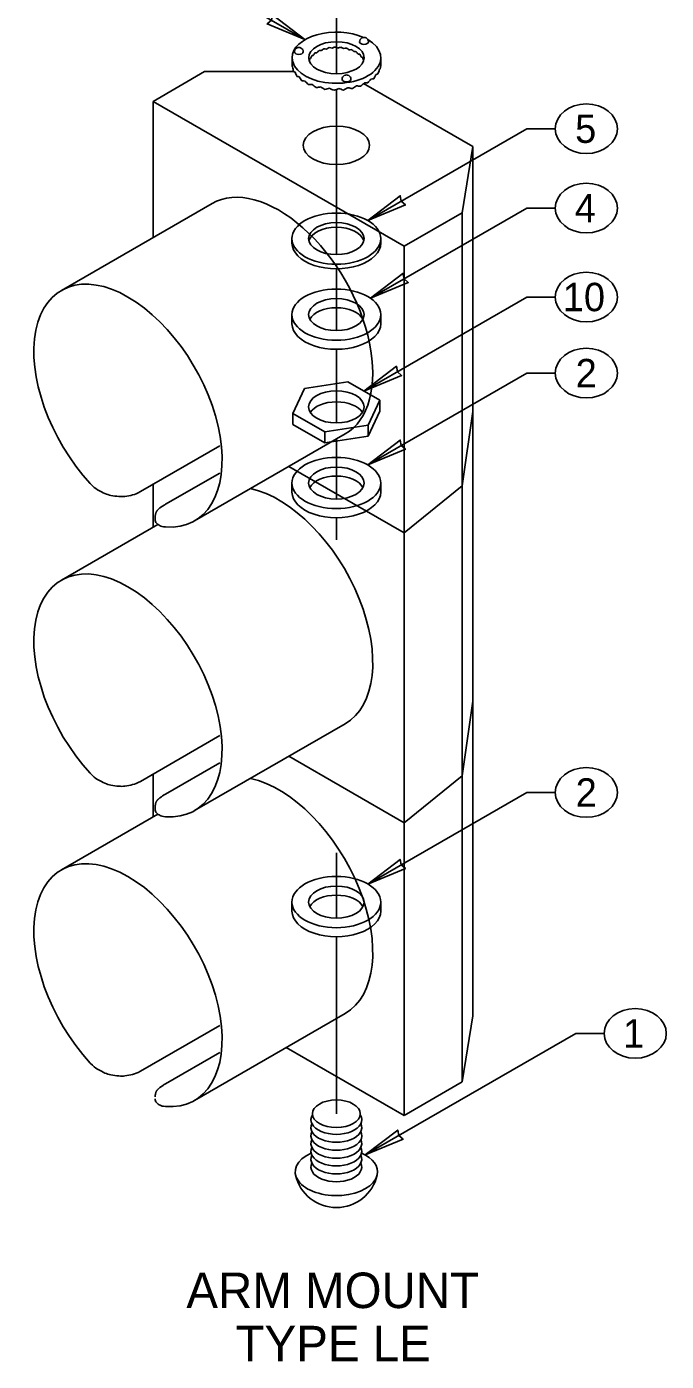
# Model space of a CAD drawing. Extents: x 99862 to 104211, y 98939 to 105076.
# Drawn here: x 100823 to 101184, y 100882 to 101635 of the extents above; entities that cross this region are included whole.
import ezdxf

# ---------------------------------------------------------------- set-up
doc = ezdxf.new("R2010")
doc.units = 0
for name, color, linetype in [('Level 1', 7, 'Continuous'), ('Level 10', 7, 'Continuous'), ('Level 15', 7, 'Continuous'), ('Level 19', 7, 'Continuous'), ('Level 2', 7, 'Continuous'), ('Level 20', 7, 'Continuous'), ('Level 26', 7, 'Continuous'), ('Level 4', 7, 'Continuous'), ('Level 5', 7, 'Continuous'), ('Level 7', 7, 'Continuous')]:
    doc.layers.add(name, color=color, linetype=linetype)

msp = doc.modelspace()

# ---------------------------------------------------------------- linework, layer by layer
at = {"layer": 'Level 1'}
msp.add_arc((100997.83, 100992.61), 23.6, 192.74663, 347.25337, dxfattribs=at)
msp.add_ellipse((100997.83, 101021.85), major_axis=(-13.49, 0), ratio=0.57735, dxfattribs=at)
for centre, major_axis, start_param, end_param in [((100997.83, 101018.51), (14.31, 0), 2.795302, 6.629476), ((100997.83, 101014.06), (14.31, 0), 2.86885, 6.555928), ((100997.83, 101009.52), (14.31, 0), 2.86338, 6.561398), ((100997.83, 101005.07), (14.31, 0), 2.86885, 6.555928), ((100997.83, 101000.71), (14.31, 0), 2.874311, 6.550467), ((100997.83, 100989.14), (23.21, 0), 2.229419, 6.153315), ((100997.83, 100996.26), (14.31, 0), 2.86885, 6.555928), ((100997.83, 100991.81), (14.31, 0), 2.86885, 6.555928), ((100997.83, 100989.14), (23.21, 0), 6.153315, 7.195359)]:
    msp.add_ellipse(centre, major_axis=major_axis, ratio=0.57735, start_param=start_param, end_param=end_param, dxfattribs=at)
at = {"layer": 'Level 10'}
for p, q in [((100979.93, 101430.54), (100973.38, 101416.43)), ((101004.38, 101434.32), (100979.93, 101430.54)), ((101022.28, 101423.99), (101004.38, 101434.32)), ((101015.73, 101409.87), (101022.28, 101423.99)), ((101022.28, 101423.99), (101022.28, 101417.79)), ((100973.38, 101416.43), (100973.38, 101410.23)), ((100973.38, 101416.43), (100991.28, 101406.09)), ((101015.73, 101403.67), (101022.28, 101417.79)), ((100973.38, 101410.23), (100991.28, 101399.89)), ((100991.28, 101406.09), (101015.73, 101409.87)), ((101015.73, 101409.87), (101015.73, 101403.67)), ((100991.28, 101406.09), (100991.28, 101399.89)), ((100991.28, 101399.89), (101015.73, 101403.67))]:
    msp.add_line(p, q, dxfattribs=at)
msp.add_ellipse((100997.83, 101420.21), major_axis=(15.66, 0), ratio=0.57735, dxfattribs=at)
msp.add_ellipse((100997.83, 101414.01), major_axis=(15.66, 0), ratio=0.57735, start_param=0.349873, end_param=2.791719, dxfattribs=at)
at = {"layer": 'Level 15'}
for p, q in [((100980.1, 101627.23), (100921.56, 101661.03)), ((100997.83, 101608), (100997.83, 101642.43)), ((100997.83, 101506.04), (100997.83, 101599.12)), ((101015.5, 101525.27), (101105.13, 101577.02)), ((101121.13, 101577.02), (101105.13, 101577.02)), ((101017.08, 101481.44), (101105.13, 101532.28)), ((101121.13, 101532.28), (101105.13, 101532.28)), ((100997.83, 101499.49), (100997.83, 101500.63)), ((100997.83, 101463.21), (100997.83, 101498.08)), ((101013.33, 101429.16), (101105.13, 101482.16)), ((101121.13, 101482.16), (101105.13, 101482.16)), ((100997.83, 101411.16), (100997.83, 101452.7)), ((101015.5, 101387.53), (101105.13, 101439.28)), ((101121.13, 101439.28), (101105.13, 101439.28)), ((100997.83, 101368.3), (100997.83, 101402.12)), ((100997.83, 101345.3), (100997.83, 101357.78)), ((101015.48, 101151.18), (101105.13, 101202.94)), ((101121.13, 101202.94), (101105.13, 101202.94)), ((100997.83, 101132.14), (100997.83, 101168.86)), ((100997.83, 101021.85), (100997.83, 101121.62)), ((101014.11, 100998.69), (101132.68, 101067.15)), ((101148.68, 101067.15), (101132.68, 101067.15))]:
    msp.add_line(p, q, dxfattribs=at)
for points in [[(100980.1, 101627.23), (100958.84, 101636.06), (100961.24, 101638.12), (100961.82, 101641.23)], [(101015.5, 101525.27), (101036.77, 101534.1), (101034.36, 101536.16), (101033.78, 101539.27)], [(101017.08, 101481.44), (101038.34, 101490.27), (101035.93, 101492.33), (101035.36, 101495.44)], [(101013.33, 101429.16), (101034.59, 101437.99), (101032.18, 101440.04), (101031.61, 101443.16)], [(101015.5, 101387.53), (101036.77, 101396.36), (101034.36, 101398.41), (101033.78, 101401.53)], [(101015.48, 101151.18), (101036.75, 101160.01), (101034.34, 101162.07), (101033.76, 101165.18)], [(101014.11, 100998.69), (101035.37, 101007.52), (101032.97, 101009.58), (101032.39, 101012.69)]]:
    msp.add_lwpolyline(points, close=True, dxfattribs=at)
at = {"layer": 'Level 19'}
for p, q in [((101068.77, 101375.67), (101074.64, 101417.67)), ((101036, 101349.19), (101068.77, 101375.67)), ((101068.77, 101212.37), (101074.64, 101254.37)), ((101036, 101185.89), (101068.77, 101212.37))]:
    msp.add_line(p, q, dxfattribs=at)
at = {"layer": 'Level 2'}
for p, q in [((100972.83, 101377.32), (100972.83, 101372.22)), ((101022.83, 101372.22), (101022.83, 101377.32)), ((100972.83, 101141.16), (100972.83, 101136.05)), ((101022.83, 101136.05), (101022.83, 101141.16))]:
    msp.add_line(p, q, dxfattribs=at)
for centre, major_axis in [((100997.83, 101377.32), (25, 0)), ((100997.83, 101377.32), (15.62, 0)), ((100997.83, 101141.16), (25, 0)), ((100997.83, 101141.16), (15.62, 0))]:
    msp.add_ellipse(centre, major_axis=major_axis, ratio=0.57735, dxfattribs=at)
for centre, major_axis, start_param, end_param in [((100997.83, 101372.22), (-15.62, 0), 3.428349, 5.996429), ((100997.83, 101372.22), (-25, 0), 6.283185, 9.424778), ((100997.83, 101136.05), (-15.62, 0), 3.428349, 5.996429), ((100997.83, 101136.05), (-25, 0), 0, 3.141593)]:
    msp.add_ellipse(centre, major_axis=major_axis, ratio=0.57735, start_param=start_param, end_param=end_param, dxfattribs=at)
at = {"layer": 'Level 20'}
for centre in [(101138.63, 101577.02), (101138.63, 101532.28), (101138.63, 101482.16), (101138.63, 101439.28), (101138.63, 101202.94), (101166.18, 101067.15)]:
    msp.add_ellipse(centre, major_axis=(-17.5, 0), ratio=0.8, dxfattribs=at)
at = {"layer": 'Level 26'}
for p, q in [((100894.58, 101592.39), (100923.64, 101609.17)), ((100973.98, 101609.17), (100923.64, 101609.17)), ((101074.64, 101566.96), (101013.19, 101602.44)), ((100894.58, 101515.7), (100894.58, 101592.39)), ((100894.58, 101592.39), (101036, 101510.74)), ((101068.77, 101529.66), (101074.64, 101566.96)), ((101074.64, 101566.96), (101074.64, 101077.06)), ((100927.79, 101534.87), (100842.94, 101485.88)), ((101036, 101510.74), (101068.77, 101529.66)), ((101068.77, 101529.66), (101068.77, 101039.76)), ((101036, 101510.74), (101036, 101020.84)), ((100917.94, 101355.98), (101002.79, 101404.97)), ((100932.21, 101398.29), (100887.51, 101372.49)), ((100971.09, 101386.66), (101036, 101349.19)), ((100894.58, 101352.4), (100894.58, 101376.57)), ((100901.65, 101365.35), (100932.11, 101382.93)), ((100897.31, 101353.97), (100842.94, 101322.58)), ((100895.79, 101357), (100895.79, 101358.04)), ((100917.94, 101192.68), (101002.79, 101241.67)), ((100887.51, 101209.19), (100932.21, 101234.99)), ((100932.11, 101219.63), (100901.65, 101202.05)), ((100971.09, 101223.36), (101036, 101185.89)), ((100894.58, 101189.1), (100894.58, 101213.27)), ((100897.31, 101190.67), (100842.94, 101159.28)), ((100895.79, 101194.74), (100895.79, 101193.7)), ((100917.94, 101029.38), (101002.79, 101078.37)), ((101068.77, 101039.76), (101074.64, 101077.06)), ((100932.21, 101071.69), (100887.51, 101045.89)), ((100901.65, 101038.75), (100932.11, 101056.33)), ((101036, 101020.84), (100969.58, 101059.19)), ((101036, 101020.84), (101068.77, 101039.76))]:
    msp.add_line(p, q, dxfattribs=at)
msp.add_ellipse((100997.83, 101567.65), major_axis=(18.75, 0), ratio=0.57735, dxfattribs=at)
for centre, start_param, end_param in [((100965.29, 101469.92), 0, 3.141593), ((100880.44, 101420.93), 5.909304, 11.369456), ((100965.29, 101306.62), 0, 2.65862), ((100880.44, 101257.63), 5.909304, 11.369456), ((100965.29, 101143.32), 0, 2.65862), ((100880.44, 101094.33), 5.909304, 11.369456)]:
    msp.add_ellipse(centre, major_axis=(37.5, -64.95), ratio=0.57735, start_param=start_param, end_param=end_param, dxfattribs=at)
for points, degree in [([(100887.51, 101372.49), (100885.6, 101371.38), (100883.33, 101370.58), (100878.37, 101369.69), (100875.69, 101369.62), (100870.42, 101370.34), (100867.8, 101371.15), (100863.09, 101373.55), (100860.98, 101375.16), (100859.23, 101377.05)], 3), ([(100895.79, 101358.03), (100895.79, 101360.36), (100897.9, 101363.19), (100901.65, 101365.35)], 2), ([(100901.65, 101352.56), (100899.9, 101352.68), (100898.46, 101353.13), (100896.42, 101354.63), (100895.84, 101355.66), (100895.8, 101356.88), (100895.8, 101356.92), (100895.8, 101356.95)], 3), ([(100859.23, 101213.75), (100860.98, 101211.86), (100863.09, 101210.25), (100867.8, 101207.85), (100870.42, 101207.05), (100875.69, 101206.32), (100878.37, 101206.39), (100883.33, 101207.28), (100885.6, 101208.08), (100887.51, 101209.19)], 3), ([(100901.65, 101202.05), (100897.9, 101199.89), (100895.79, 101197.06), (100895.79, 101194.73)], 2), ([(100895.8, 101193.65), (100895.8, 101193.62), (100895.8, 101193.58), (100895.84, 101192.36), (100896.42, 101191.33), (100898.46, 101189.83), (100899.9, 101189.39), (100901.65, 101189.26)], 3), ([(100887.51, 101045.89), (100885.6, 101044.78), (100883.33, 101043.98), (100878.37, 101043.09), (100875.69, 101043.02), (100870.42, 101043.75), (100867.8, 101044.55), (100863.09, 101046.95), (100860.98, 101048.56), (100859.23, 101050.45)], 3), ([(100895.79, 101031.43), (100895.79, 101033.76), (100897.9, 101036.59), (100901.65, 101038.75)], 2), ([(100901.65, 101025.96), (100899.9, 101026.09), (100898.46, 101026.54), (100896.42, 101028.03), (100895.84, 101029.06), (100895.8, 101030.28), (100895.8, 101030.32), (100895.8, 101030.36)], 3)]:
    msp.add_open_spline(points, degree=degree, dxfattribs=at)
at = {"layer": 'Level 4'}
for p, q in [((100972.83, 101472.24), (100972.83, 101467.13)), ((101022.83, 101467.13), (101022.83, 101472.24))]:
    msp.add_line(p, q, dxfattribs=at)
for major_axis in [(25, 0), (15.62, 0)]:
    msp.add_ellipse((100997.83, 101472.24), major_axis=major_axis, ratio=0.57735, dxfattribs=at)
for major_axis, start_param, end_param in [((-15.62, 0), 3.428349, 5.996429), ((-25, 0), 0, 3.141593)]:
    msp.add_ellipse((100997.83, 101467.13), major_axis=major_axis, ratio=0.57735, start_param=start_param, end_param=end_param, dxfattribs=at)
at = {"layer": 'Level 5'}
for p, q in [((100972.83, 101515.07), (100972.83, 101512.51)), ((100982.2, 101515.07), (100982.2, 101514.84)), ((101022.83, 101512.51), (101022.83, 101515.07))]:
    msp.add_line(p, q, dxfattribs=at)
for major_axis in [(25, 0), (15.62, 0)]:
    msp.add_ellipse((100997.83, 101515.07), major_axis=major_axis, ratio=0.57735, dxfattribs=at)
for major_axis, start_param, end_param in [((-15.62, 0), 3.28349, 6.141288), ((-25, 0), 0, 3.141593)]:
    msp.add_ellipse((100997.83, 101512.51), major_axis=major_axis, ratio=0.57735, start_param=start_param, end_param=end_param, dxfattribs=at)
at = {"layer": 'Level 7'}
for p, q in [((100972.88, 101617.02), (100972.88, 101613.56)), ((101022.88, 101613.56), (101022.88, 101617.02))]:
    msp.add_line(p, q, dxfattribs=at)
for centre in [(101013.38, 101625.99), (100976.7, 101620.32), (101003.55, 101604.81)]:
    msp.add_arc(centre, 2.5, 0, 180.52077, dxfattribs=at)
for centre, major_axis, ratio, start_param, end_param in [((100997.88, 101617.02), (-25, 0), 0.57735, 4.057662, 6.283185), ((100997.88, 101617.02), (-25, 0), 0.57735, 0, 3.927598), ((101013.38, 101625.97), (-2.5, 0), 0.57735, 0.005248, 3.136345), ((100976.7, 101620.3), (-2.5, 0), 0.57735, 0.005248, 3.136345), ((100997.88, 101614.05), (13.71, 9.15), 0.818147, 2.17058, 2.2753), ((100997.88, 101614.05), (-15.61, 2.82), 0.236491, 5.749859, 5.854579), ((100997.88, 101614.05), (13.95, 9.4), 0.749264, 1.993037, 2.097757), ((100997.88, 101614.05), (-15.59, 3.98), 0.270119, 5.566662, 5.671382), ((100997.88, 101614.05), (14.27, 9.33), 0.682966, 1.831273, 1.935992), ((100997.88, 101614.05), (-15.54, 5.06), 0.312139, 5.389669, 5.494389), ((100997.88, 101614.05), (14.58, 9.06), 0.6191, 1.675068, 1.779788), ((100997.88, 101614.05), (-15.47, 6.05), 0.360362, 5.218891, 5.323611), ((100997.88, 101614.05), (14.87, 8.62), 0.557438, 1.520168, 1.624888), ((100997.88, 101614.05), (-15.36, 6.93), 0.413044, 5.053719, 5.158439), ((100997.88, 101614.05), (15.1, 8.04), 0.497899, 1.364205, 1.468924), ((100997.88, 101614.05), (-15.2, 7.7), 0.468967, 4.893172, 4.997892), ((100997.88, 101614.05), (15.29, 7.33), 0.440657, 1.205527, 1.310247), ((100997.88, 101614.05), (-14.99, 8.34), 0.527399, 4.736033, 4.840753), ((100997.88, 101614.05), (15.42, 6.5), 0.386234, 1.042807, 1.147526), ((100997.88, 101614.05), (-14.73, 8.85), 0.588004, 4.580838, 4.685558), ((100997.88, 101614.05), (15.51, 5.57), 0.335596, 0.874936, 0.979655), ((100997.88, 101614.05), (-14.43, 9.22), 0.650745, 4.426002, 4.530376), ((100997.88, 101614.05), (15.57, 4.51), 0.292084, 0.70101, 0.806075), ((100997.88, 101614.05), (-14.13, 9.33), 0.716006, 4.263599, 4.368664), ((100997.88, 101614.05), (15.6, 3.41), 0.252109, 0.520948, 0.625322), ((100997.88, 101614.05), (-13.81, 9.33), 0.783391, 4.099781, 4.204501), ((100997.88, 101614.05), (15.62, 2.21), 0.223561, 0.334923, 0.439643), ((100997.88, 101614.05), (-13.7, 8.8), 0.853385, 3.904606, 4.009326), ((100997.88, 101614.05), (-24.57, -4.88), 0.947565, 6.097095, 6.149455), ((100997.88, 101614.05), (-25, -1.53), 0.206802, 0.039705, 0.144424), ((100997.88, 101614.05), (22.99, -10.64), 0.922162, 3.702024, 3.806744), ((100997.88, 101614.05), (-24.99, -3.53), 0.223561, 0.230203, 0.334923), ((100997.88, 101614.05), (13.86, 8.11), 0.888613, 2.400234, 2.472416), ((100997.88, 101614.05), (-15.62, 1.59), 0.213589, 5.93836, 6.04308), ((100997.88, 101614.05), (15.62, 0.96), 0.206802, 0.157505, 0.249144), ((100997.88, 101614.05), (-22.18, -12.98), 0.888613, 2.295514, 2.400234), ((100997.88, 101614.05), (24.99, -2.54), 0.213589, 6.04308, 6.1478), ((100997.88, 101614.05), (-24.57, -4.88), 0.947565, 2.798423, 2.903143), ((100997.88, 101614.05), (25, -0.51), 0.203365, 6.234982, 6.287342), ((100997.88, 101614.05), (21.92, -14.08), 0.853385, 4.009326, 4.114045), ((100997.88, 101614.05), (-24.96, -5.45), 0.252109, 0.416228, 0.520948), ((100997.88, 101614.05), (22.09, -14.93), 0.783391, 4.204501, 4.308875), ((100997.88, 101614.05), (-24.91, -7.21), 0.292084, 0.595944, 0.70101), ((100997.88, 101614.05), (22.6, -14.92), 0.716006, 4.368664, 4.47373), ((100997.88, 101614.05), (-24.82, -8.91), 0.335596, 0.770561, 0.874936), ((100997.88, 101614.05), (23.09, -14.75), 0.650745, 4.530376, 4.635096), ((101003.55, 101604.8), (-2.5, 0), 0.57735, 0.005248, 3.136345), ((100997.88, 101614.05), (-22.83, -14.93), 0.682966, 1.726553, 1.831273), ((100997.88, 101614.05), (24.87, -8.1), 0.312139, 5.494389, 5.599109), ((100997.88, 101614.05), (-22.31, -15.05), 0.749264, 1.888318, 1.993037), ((100997.88, 101614.05), (24.94, -6.37), 0.270119, 5.671382, 5.776101), ((100997.88, 101614.05), (-21.94, -14.64), 0.818147, 2.06586, 2.17058), ((100997.88, 101614.05), (24.98, -4.51), 0.236491, 5.854579, 5.959298), ((100997.88, 101614.05), (-24.67, -10.41), 0.386234, 0.938087, 1.042807), ((100997.88, 101614.05), (23.57, -14.17), 0.588004, 4.685558, 4.790278), ((100997.88, 101614.05), (-24.46, -11.73), 0.440657, 1.100807, 1.205527), ((100997.88, 101614.05), (23.99, -13.35), 0.527399, 4.840753, 4.945473), ((100997.88, 101614.05), (-24.17, -12.86), 0.497899, 1.259485, 1.364205), ((100997.88, 101614.05), (24.32, -12.32), 0.468967, 4.997892, 5.102611), ((100997.88, 101614.05), (-23.79, -13.78), 0.557438, 1.415448, 1.520168), ((100997.88, 101614.05), (24.58, -11.09), 0.413044, 5.158439, 5.263158), ((100997.88, 101614.05), (-23.34, -14.49), 0.6191, 1.570348, 1.675068), ((100997.88, 101614.05), (24.76, -9.68), 0.360362, 5.323611, 5.42833)]:
    msp.add_ellipse(centre, major_axis=major_axis, ratio=ratio, start_param=start_param, end_param=end_param, dxfattribs=at)
msp.add_ellipse((100997.88, 101617.02), major_axis=(-15.63, 0), ratio=0.57735, dxfattribs=at)

# ---------------------------------------------------------------- texts
at = {"layer": 'Level 20'}
for s, height, p in [('5', 16, (101132.32, 101569.02)), ('4', 16, (101132.12, 101524.29)), ('10', 16, (101125.38, 101474.16)), ('2', 16, (101132.64, 101431.28)), ('2', 16, (101132.64, 101194.94)), ('1', 16, (101159.31, 101059.15)), ('ARM MOUNT', 20, (100913.32, 100912.35)), ('TYPE LE', 20, (100941.04, 100882.35))]:
    msp.add_text(s, height=height, dxfattribs=at).set_placement(p)

doc.saveas('drawing.dxf')
